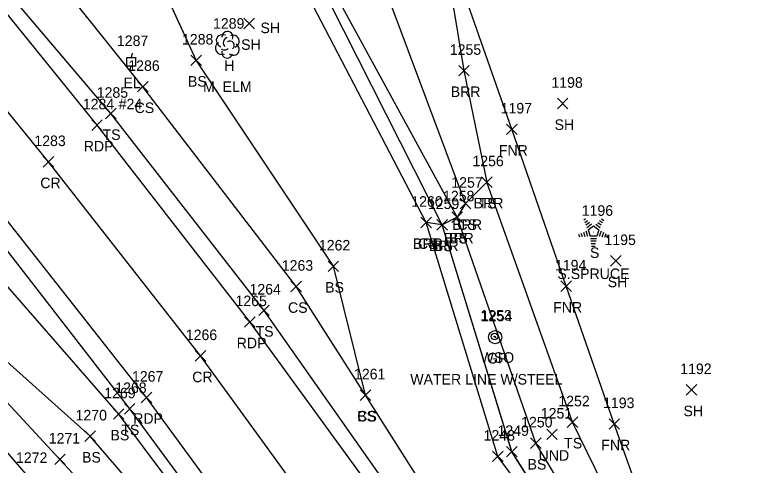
# Model space of a CAD drawing. Extents: x 1415642 to 1422021, y 544543 to 547232.
# Drawn here: x 1416364 to 1416506.8, y 546547.3 to 546632.9 of the extents above; entities that cross this region are included whole.
import ezdxf

# ---------------------------------------------------------------- set-up
doc = ezdxf.new("R2010")
doc.units = 0
for name, color, linetype in [('D_A', 7, 'Continuous'), ('D_I', 7, 'Continuous'), ('D_TIC', 7, 'Continuous'), ('L_A', 7, 'Continuous'), ('L_C', 7, 'Continuous'), ('L_I', 7, 'Continuous'), ('L_TIC', 7, 'Continuous'), ('LABL', 7, 'Continuous'), ('LAWA', 7, 'Continuous'), ('LELB', 7, 'Continuous'), ('LFNC', 7, 'Continuous'), ('LTC', 7, 'Continuous'), ('LTD', 7, 'Continuous'), ('P_A', 7, 'Continuous'), ('P_I', 7, 'Continuous'), ('P_TIC', 7, 'Continuous'), ('PET', 7, 'Continuous'), ('PRC', 7, 'Continuous'), ('R_A', 7, 'Continuous'), ('R_C', 7, 'Continuous'), ('R_I', 7, 'Continuous'), ('RGP', 7, 'Continuous'), ('U_A', 7, 'Continuous'), ('U_C', 7, 'Continuous'), ('U_I', 7, 'Continuous'), ('UEPT', 7, 'Continuous'), ('UWV', 7, 'Continuous')]:
    doc.layers.add(name, color=color, linetype=linetype)

msp = doc.modelspace()

# ---------------------------------------------------------------- linework, layer by layer
at = {"layer": 'D_TIC'}
for points in [[(1416464.81, 546552.27), (1416466.81, 546554.27)], [(1416466.81, 546552.27), (1416464.81, 546554.27)]]:
    msp.add_lwpolyline(points, dxfattribs=at)
at = {"layer": 'L_TIC'}
for points in [[(1416407.37, 546630.27), (1416409.37, 546632.27)], [(1416409.37, 546630.27), (1416407.37, 546632.27)], [(1416397.34, 546623.28), (1416399.34, 546625.28)], [(1416399.34, 546623.28), (1416397.34, 546625.28)], [(1416448.12, 546621.32), (1416450.12, 546623.32)], [(1416450.12, 546621.32), (1416448.12, 546623.32)], [(1416387.22, 546618.27), (1416389.22, 546620.27)], [(1416389.22, 546618.27), (1416387.22, 546620.27)], [(1416466.83, 546615.07), (1416468.83, 546617.07)], [(1416468.83, 546615.07), (1416466.83, 546617.07)], [(1416381.17, 546613.17), (1416383.17, 546615.17)], [(1416383.17, 546613.17), (1416381.17, 546615.17)], [(1416457.21, 546610.19), (1416459.21, 546612.19)], [(1416459.21, 546610.19), (1416457.21, 546612.19)], [(1416452.47, 546600.16), (1416454.47, 546602.16)], [(1416454.47, 546600.16), (1416452.47, 546602.16)], [(1416452.47, 546600.16), (1416454.47, 546602.16)], [(1416454.47, 546600.16), (1416452.47, 546602.16)], [(1416448.42, 546596.09), (1416450.42, 546598.09)], [(1416450.42, 546596.09), (1416448.42, 546598.09)], [(1416448.42, 546596.09), (1416450.42, 546598.09)], [(1416450.42, 546596.09), (1416448.42, 546598.09)], [(1416446.84, 546593.51), (1416448.84, 546595.51)], [(1416448.84, 546593.51), (1416446.84, 546595.51)], [(1416446.84, 546593.51), (1416448.84, 546595.51)], [(1416448.84, 546593.51), (1416446.84, 546595.51)], [(1416440.96, 546592.48), (1416442.96, 546594.48)], [(1416442.96, 546592.48), (1416440.96, 546594.48)], [(1416440.96, 546592.48), (1416442.96, 546594.48)], [(1416442.96, 546592.48), (1416440.96, 546594.48)], [(1416443.98, 546592.05), (1416445.98, 546594.05)], [(1416445.98, 546592.05), (1416443.98, 546594.05)], [(1416443.98, 546592.05), (1416445.98, 546594.05)], [(1416445.98, 546592.05), (1416443.98, 546594.05)], [(1416476.9, 546585.21), (1416478.9, 546587.21)], [(1416478.9, 546585.21), (1416476.9, 546587.21)], [(1416423.35, 546584.18), (1416425.35, 546586.18)], [(1416425.35, 546584.18), (1416423.35, 546586.18)], [(1416416.31, 546580.34), (1416418.31, 546582.34)], [(1416418.31, 546580.34), (1416416.31, 546582.34)], [(1416467.51, 546580.39), (1416469.51, 546582.39)], [(1416469.51, 546580.39), (1416467.51, 546582.39)], [(1416410.19, 546575.82), (1416412.19, 546577.82)], [(1416412.19, 546575.82), (1416410.19, 546577.82)], [(1416491.25, 546560.72), (1416493.25, 546562.72)], [(1416493.25, 546560.72), (1416491.25, 546562.72)], [(1416429.44, 546559.72), (1416431.44, 546561.72)], [(1416431.44, 546559.72), (1416429.44, 546561.72)], [(1416429.44, 546559.72), (1416431.44, 546561.72)], [(1416431.44, 546559.72), (1416429.44, 546561.72)], [(1416382.64, 546556.13), (1416384.64, 546558.13)], [(1416384.64, 546556.13), (1416382.64, 546558.13)], [(1416384.73, 546557.12), (1416386.73, 546559.12)], [(1416386.73, 546557.12), (1416384.73, 546559.12)], [(1416468.71, 546554.6), (1416470.71, 546556.6)], [(1416470.71, 546554.6), (1416468.71, 546556.6)], [(1416476.63, 546554.25), (1416478.63, 546556.25)], [(1416478.63, 546554.25), (1416476.63, 546556.25)], [(1416377.25, 546551.92), (1416379.25, 546553.92)], [(1416379.25, 546551.92), (1416377.25, 546553.92)], [(1416461.74, 546550.59), (1416463.74, 546552.59)], [(1416463.74, 546550.59), (1416461.74, 546552.59)], [(1416457.18, 546548.98), (1416459.18, 546550.98)], [(1416459.18, 546548.98), (1416457.18, 546550.98)], [(1416371.51, 546547.53), (1416373.51, 546549.53)], [(1416373.51, 546547.53), (1416371.51, 546549.53)], [(1416454.53, 546548.09), (1416456.53, 546550.09)], [(1416456.53, 546548.09), (1416454.53, 546550.09)]]:
    msp.add_lwpolyline(points, dxfattribs=at)
at = {"layer": 'LABL'}
for points in [[(1416444.47, 546650.39), (1416449.12, 546622.32), (1416453.47, 546601.16), (1416449.42, 546597.09), (1416447.84, 546594.51), (1416444.98, 546593.05), (1416441.96, 546593.48), (1416418.31, 546638.92), (1416405.03, 546665.65), (1416399.91, 546654.53), (1416396.19, 546650.28), (1416389.66, 546643.26), (1416382.8, 546639.59), (1416370.88, 546651.88), (1416331.53, 546697.52), (1416315.15, 546719.28), (1416313.42, 546715.93), (1416308.55, 546724.26), (1416301.62, 546736.74), (1416278.11, 546774.25)], [(1416444.47, 546650.39), (1416449.12, 546622.32), (1416453.47, 546601.16), (1416449.42, 546597.08), (1416447.84, 546594.51), (1416444.98, 546593.04), (1416441.96, 546593.48), (1416418.31, 546638.92), (1416405.03, 546665.65), (1416399.91, 546654.53), (1416396.19, 546650.28), (1416389.66, 546643.27), (1416382.81, 546639.59), (1416370.88, 546651.88), (1416331.54, 546697.52), (1416315.15, 546719.28), (1416313.42, 546715.93), (1416308.55, 546724.26), (1416301.62, 546736.74), (1416278.12, 546774.25)]]:
    msp.add_lwpolyline(points, dxfattribs=at)
at = {"layer": 'LAWA'}
msp.add_lwpolyline([(1416366.86, 546544.85), (1416337.81, 546578.41)], dxfattribs=at)
msp.add_lwpolyline([(1416366.86, 546544.85), (1416337.81, 546578.41)], dxfattribs=at)
at = {"layer": 'LELB'}
for points in [[(1416413.88, 546519.84), (1416385.73, 546558.12), (1416356.85, 546595.36), (1416336.82, 546621.39), (1416300.66, 546661.66), (1416278.22, 546684.25), (1416249.88, 546714.04), (1416230.93, 546728.9), (1416221.86, 546737.5), (1416200.69, 546756.25), (1416176.24, 546778.44), (1416157.26, 546793.38), (1416140.02, 546808.9), (1416121.84, 546825.58), (1416090.2, 546848.7), (1416061.67, 546872.28), (1416021.03, 546902.96), (1415979.27, 546932.57), (1415964.6, 546940.59)], [(1416413.88, 546519.84), (1416385.73, 546558.12), (1416356.85, 546595.36), (1416336.82, 546621.39), (1416300.66, 546661.66), (1416278.22, 546684.25), (1416249.88, 546714.04), (1416230.93, 546728.9), (1416221.87, 546737.51), (1416200.69, 546756.25), (1416176.24, 546778.44), (1416157.26, 546793.38), (1416140.03, 546808.9), (1416121.84, 546825.58), (1416090.21, 546848.7), (1416061.68, 546872.28), (1416021.04, 546902.96), (1415979.28, 546932.57), (1415964.61, 546940.59)], [(1416487.57, 546505.93), (1416480.71, 546505.12), (1416469.86, 546502.72), (1416462.76, 546510.55), (1416442.83, 546541.19), (1416430.44, 546560.72), (1416424.35, 546585.18), (1416398.34, 546624.28), (1416389.66, 546643.26), (1416377.3, 546653.03), (1416344.54, 546704.05), (1416343.42, 546724.77), (1416329.35, 546768.04), (1416303.68, 546799.52), (1416274.8, 546819.39), (1416239.26, 546839.41), (1416210.61, 546845.46), (1416203.47, 546849.21), (1416195, 546854.49)], [(1416487.57, 546505.93), (1416480.71, 546505.12), (1416469.86, 546502.72), (1416462.76, 546510.55), (1416442.83, 546541.19), (1416430.44, 546560.72), (1416424.35, 546585.18), (1416398.34, 546624.28), (1416389.66, 546643.27), (1416377.3, 546653.03), (1416344.54, 546704.05), (1416343.42, 546724.76), (1416329.35, 546768.04), (1416303.68, 546799.52), (1416274.8, 546819.4), (1416239.26, 546839.41), (1416210.61, 546845.46), (1416203.48, 546849.21), (1416195, 546854.49)], [(1416488.29, 546504.83), (1416488.12, 546506.46), (1416480.5, 546522.11), (1416462.74, 546551.59), (1416447.84, 546594.51), (1416422.44, 546641.16), (1416410.18, 546676.27), (1416393.07, 546713.79), (1416378.8, 546749.63), (1416367.97, 546783.97), (1416347.35, 546811.63), (1416340.26, 546839.45), (1416338.76, 546849.28)], [(1416488.29, 546504.83), (1416488.12, 546506.46), (1416480.5, 546522.11), (1416462.74, 546551.59), (1416447.84, 546594.51), (1416422.44, 546641.16), (1416410.17, 546676.27), (1416393.07, 546713.79), (1416378.8, 546749.63), (1416367.97, 546783.97), (1416347.34, 546811.63), (1416340.26, 546839.45), (1416338.76, 546849.28)], [(1416449.42, 546597.09), (1416431.29, 546645.7), (1416419.63, 546678.87), (1416400.37, 546718.89), (1416388.41, 546748.65), (1416375.25, 546786.59), (1416353.32, 546816.02), (1416347.15, 546837.59)], [(1416449.42, 546597.08), (1416431.29, 546645.7), (1416419.63, 546678.87), (1416400.37, 546718.89), (1416388.42, 546748.65), (1416375.25, 546786.59), (1416353.33, 546816.03), (1416347.15, 546837.59)], [(1416462.64, 546496.11), (1416437.87, 546538.89), (1416411.19, 546576.82), (1416382.17, 546614.17), (1416360.8, 546639.39), (1416323.65, 546683.15), (1416301.53, 546707.03), (1416273.6, 546735.69), (1416258.67, 546751.22), (1416224.41, 546784.74), (1416201.13, 546806.07), (1416169.09, 546832.26)], [(1416462.64, 546496.11), (1416437.87, 546538.89), (1416411.18, 546576.82), (1416382.17, 546614.17), (1416360.8, 546639.39), (1416323.65, 546683.15), (1416301.53, 546707.03), (1416273.6, 546735.69), (1416258.67, 546751.22), (1416224.4, 546784.74), (1416201.13, 546806.07), (1416169.09, 546832.26)], [(1416578, 546177.77), (1416578.55, 546199.27), (1416573.9, 546214.14), (1416552.43, 546269), (1416536.22, 546304.5), (1416520.22, 546335.71), (1416500.65, 546371.21), (1416484.25, 546405.14), (1416455.06, 546455.78), (1416435.93, 546486.65), (1416412.14, 546519.01), (1416383.64, 546557.13), (1416352.74, 546592.54), (1416331.82, 546618.14), (1416293.94, 546655.61), (1416274.22, 546680.91), (1416245.72, 546708.98), (1416224.27, 546729.93), (1416198.14, 546753.3), (1416170.94, 546765.48), (1416158.5, 546767.31), (1416141.08, 546772.75), (1416136.01, 546776.95), (1416129, 546780.64)], [(1416578, 546177.77), (1416578.55, 546199.27), (1416573.9, 546214.14), (1416552.42, 546269.01), (1416536.22, 546304.5), (1416520.22, 546335.71), (1416500.65, 546371.22), (1416484.25, 546405.15), (1416455.06, 546455.79), (1416435.93, 546486.65), (1416412.14, 546519.01), (1416383.65, 546557.13), (1416352.74, 546592.54), (1416331.82, 546618.14), (1416293.94, 546655.62), (1416274.22, 546680.91), (1416245.72, 546708.98), (1416224.27, 546729.93), (1416198.14, 546753.3), (1416170.94, 546765.48), (1416158.51, 546767.31), (1416141.09, 546772.75), (1416136.01, 546776.96), (1416129.01, 546780.64)], [(1416503.76, 546247.98), (1416498.74, 546274.69), (1416501.23, 546308.66), (1416502.98, 546324.04), (1416489.47, 546365.32), (1416480.57, 546403.46), (1416453.11, 546455.02), (1416433.2, 546484.78), (1416409.26, 546516.78), (1416378.25, 546552.92), (1416343.61, 546583.91), (1416327.57, 546614.09), (1416289.4, 546651.59), (1416267.58, 546675.69), (1416237.14, 546697.31), (1416220.66, 546725.9), (1416195.41, 546750.9), (1416170.78, 546763.33), (1416158.82, 546764.49), (1416140.16, 546770.72), (1416135.4, 546775.05), (1416128.27, 546778.63)], [(1416503.76, 546247.98), (1416498.74, 546274.69), (1416501.24, 546308.65), (1416502.98, 546324.03), (1416489.47, 546365.32), (1416480.57, 546403.46), (1416453.11, 546455.02), (1416433.2, 546484.78), (1416409.26, 546516.79), (1416378.25, 546552.92), (1416343.61, 546583.91), (1416327.58, 546614.09), (1416289.4, 546651.59), (1416267.58, 546675.69), (1416237.14, 546697.31), (1416220.66, 546725.9), (1416195.42, 546750.9), (1416170.78, 546763.33), (1416158.81, 546764.5), (1416140.16, 546770.72), (1416135.4, 546775.05), (1416128.28, 546778.62)], [(1416488.29, 546504.83), (1416487.21, 546504.52), (1416487.57, 546505.93), (1416477.24, 546519.91), (1416458.18, 546549.98), (1416444.98, 546593.05), (1416421.02, 546640.5), (1416406.73, 546674.57), (1416393.07, 546713.79)], [(1416488.29, 546504.83), (1416487.21, 546504.52), (1416487.57, 546505.93), (1416477.24, 546519.91), (1416458.18, 546549.99), (1416444.98, 546593.04), (1416421.01, 546640.5), (1416406.73, 546674.57), (1416393.07, 546713.79)], [(1416430.44, 546560.72), (1416417.31, 546581.34), (1416388.22, 546619.27), (1416367.45, 546645.31), (1416327.63, 546687.63), (1416307.15, 546711.36)], [(1416430.44, 546560.72), (1416417.31, 546581.35), (1416388.22, 546619.27), (1416367.44, 546645.31), (1416327.63, 546687.64), (1416307.15, 546711.36)], [(1416480.57, 546403.46), (1416449.3, 546452.17), (1416431.01, 546483.64), (1416405.55, 546512.84), (1416372.51, 546548.53), (1416341.49, 546581.99), (1416324.84, 546612.16), (1416286, 546648.13), (1416263.12, 546671.71)], [(1416480.57, 546403.46), (1416449.3, 546452.17), (1416431.01, 546483.64), (1416405.56, 546512.84), (1416372.51, 546548.53), (1416341.49, 546581.99), (1416324.84, 546612.16), (1416286, 546648.13), (1416263.12, 546671.71)], [(1416493.36, 546510.33), (1416486.81, 546520.52), (1416469.71, 546555.6), (1416453.47, 546601.16)], [(1416493.36, 546510.33), (1416486.82, 546520.52), (1416469.71, 546555.59), (1416453.47, 546601.16)], [(1416477.24, 546519.91), (1416455.53, 546549.09), (1416441.96, 546593.48)], [(1416477.24, 546519.91), (1416455.53, 546549.1), (1416441.96, 546593.48)]]:
    msp.add_lwpolyline(points, dxfattribs=at)
at = {"layer": 'LFNC'}
for points in [[(1416506.5, 546506.54), (1416496.1, 546503.23), (1416493.36, 546510.33), (1416488.7, 546524.12), (1416477.63, 546555.25), (1416468.51, 546581.39), (1416458.21, 546611.19), (1416444.47, 546650.39), (1416432.95, 546683.5)], [(1416506.5, 546506.54), (1416496.1, 546503.23), (1416493.36, 546510.33), (1416488.7, 546524.12), (1416477.63, 546555.24), (1416468.51, 546581.39), (1416458.21, 546611.19), (1416444.47, 546650.39), (1416432.95, 546683.5)]]:
    msp.add_lwpolyline(points, dxfattribs=at)
at = {"layer": 'LTC'}
for p, q in [((1416471.83, 546593.97), (1416472.18, 546594.22)), ((1416472.03, 546593.5), (1416472.56, 546593.89)), ((1416474.85, 546593.86), (1416475.4, 546593.46)), ((1416475.22, 546594.21), (1416475.64, 546593.9)), ((1416472.24, 546593.04), (1416472.95, 546593.55)), ((1416472.45, 546592.57), (1416473.33, 546593.21)), ((1416472.68, 546592.11), (1416473.69, 546592.85)), ((1416473.69, 546592.85), (1416474.69, 546592.12)), ((1416474.11, 546593.16), (1416474.92, 546592.57)), ((1416474.48, 546593.51), (1416475.16, 546593.02)), ((1416470.86, 546591.25), (1416471.01, 546590.78)), ((1416471.31, 546591.46), (1416471.52, 546590.81)), ((1416471.77, 546591.68), (1416472.04, 546590.84)), ((1416472.22, 546591.9), (1416472.55, 546590.88)), ((1416472.68, 546592.11), (1416473.07, 546590.92)), ((1416474.3, 546590.92), (1416473.07, 546590.92)), ((1416474.69, 546592.12), (1416474.3, 546590.92)), ((1416475.12, 546591.85), (1416474.79, 546590.81)), ((1416475.57, 546591.6), (1416475.28, 546590.72)), ((1416476.01, 546591.35), (1416475.78, 546590.62)), ((1416476.46, 546591.1), (1416476.27, 546590.53)), ((1416474.26, 546590.42), (1416473.11, 546590.42)), ((1416474.17, 546589.92), (1416473.19, 546589.92)), ((1416474.09, 546589.42), (1416473.26, 546589.42)), ((1416474.01, 546588.92), (1416473.33, 546588.92))]:
    msp.add_line(p, q, dxfattribs=at)
at = {"layer": 'LTD'}
msp.add_line((1416404.23, 546627.28), (1416404.23, 546627.28), dxfattribs=at)
msp.add_line((1416404.23, 546627.28), (1416404.23, 546627.28), dxfattribs=at)
msp.add_arc((1416404.27, 546628.71), 1.05, 335.5272, 180.9563, dxfattribs=at)
for centre, major_axis, ratio, start_param, end_param in [((1416403.44, 546627.95), (1.21, -0.51), 0.895232, 1.570796, 4.712389), ((1416404.02, 546627.74), (-0.208, -0.792), 0.645439, 3.141593, 6.283185), ((1416404.73, 546627.11), (-0.5, 0.667), 0.989748, 3.141593, 6.283185), ((1416405.27, 546627.86), (-1.14, -0.48), 0.949671, 1.570796, 4.712389), ((1416403.14, 546626.57), (0.58, -1.04), 0.959034, 3.141593, 6.283185), ((1416403.77, 546626.53), (-0.625, -0.083), 0.423636, 0, 3.141593), ((1416405.23, 546626.45), (-1.09, 0.79), 0.841452, 1.570796, 4.712389), ((1416404.23, 546625.78), (0.26, 1.06), 0.942809, 1.570796, 4.712389)]:
    msp.add_ellipse(centre, major_axis=major_axis, ratio=ratio, start_param=start_param, end_param=end_param, dxfattribs=at)
at = {"layer": 'P_TIC'}
for points in [[(1416378.54, 546610.97), (1416380.54, 546612.97)], [(1416380.54, 546610.97), (1416378.54, 546612.97)], [(1416369.34, 546604), (1416371.34, 546606)], [(1416371.34, 546604), (1416369.34, 546606)], [(1416407.53, 546573.61), (1416409.53, 546575.61)], [(1416409.53, 546573.61), (1416407.53, 546575.61)], [(1416398.16, 546567.17), (1416400.16, 546569.17)], [(1416400.16, 546567.17), (1416398.16, 546569.17)], [(1416387.9, 546559.28), (1416389.9, 546561.28)], [(1416389.9, 546559.28), (1416387.9, 546561.28)]]:
    msp.add_lwpolyline(points, dxfattribs=at)
at = {"layer": 'PET'}
for points in [[(1416435.56, 546537.44), (1416408.53, 546574.61), (1416379.54, 546611.97), (1416358.62, 546637.86), (1416320.38, 546681.18), (1416299.04, 546704.62), (1416270.68, 546734.26), (1416256.1, 546749.21), (1416221.42, 546781.44), (1416197.8, 546803.68), (1416167.45, 546829.93), (1416146.9, 546847.39), (1416116.66, 546870.72), (1416088.42, 546892.72), (1416062.97, 546911.59), (1416031.6, 546935.61), (1415998.08, 546959.73), (1415969.06, 546981.93), (1415936.64, 547006.92)], [(1416435.56, 546537.44), (1416408.53, 546574.62), (1416379.54, 546611.97), (1416358.63, 546637.85), (1416320.38, 546681.18), (1416299.04, 546704.62), (1416270.69, 546734.26), (1416256.1, 546749.21), (1416221.42, 546781.44), (1416197.8, 546803.68), (1416167.45, 546829.93), (1416146.9, 546847.38), (1416116.66, 546870.72), (1416088.42, 546892.72), (1416062.98, 546911.58), (1416031.6, 546935.61), (1415998.08, 546959.73), (1415969.07, 546981.93), (1415936.65, 547006.92)], [(1416417.68, 546520.98), (1416388.9, 546560.28), (1416359.4, 546597.75), (1416339.06, 546622.92), (1416303.08, 546664.45), (1416282.37, 546687.64), (1416253.58, 546717.16), (1416237.44, 546733.28), (1416206.51, 546762.17), (1416181.86, 546784.67), (1416151.94, 546810.47), (1416130.39, 546828.26), (1416101.49, 546851.34), (1416072.78, 546874.03), (1416047.41, 546892.82), (1416017.81, 546915.59), (1415982.21, 546942.39), (1415954.4, 546964.56)], [(1416417.68, 546520.98), (1416388.9, 546560.28), (1416359.4, 546597.76), (1416339.06, 546622.93), (1416303.08, 546664.45), (1416282.37, 546687.65), (1416253.58, 546717.16), (1416237.44, 546733.28), (1416206.51, 546762.17), (1416181.87, 546784.67), (1416151.94, 546810.47), (1416130.39, 546828.26), (1416101.49, 546851.34), (1416072.78, 546874.03), (1416047.41, 546892.82), (1416017.81, 546915.59), (1415982.21, 546942.39), (1415954.4, 546964.56)]]:
    msp.add_lwpolyline(points, dxfattribs=at)
at = {"layer": 'PRC'}
for points in [[(1416425.29, 546532.23), (1416399.16, 546568.17), (1416370.34, 546605), (1416349.98, 546630.03), (1416312.55, 546673.44), (1416291.21, 546696.63), (1416262.58, 546725.99), (1416246.66, 546742.06), (1416214.68, 546772.43), (1416190.4, 546794.67), (1416160.38, 546819.82), (1416139.01, 546837.64), (1416109.6, 546860.71), (1416080.51, 546883.13), (1416051.44, 546902.01), (1416024.84, 546926.07), (1415989.92, 546951.67), (1415962.46, 546973.18)], [(1416425.29, 546532.24), (1416399.16, 546568.17), (1416370.35, 546605), (1416349.98, 546630.03), (1416312.55, 546673.45), (1416291.21, 546696.63), (1416262.58, 546725.99), (1416246.66, 546742.06), (1416214.67, 546772.43), (1416190.4, 546794.67), (1416160.38, 546819.82), (1416139.01, 546837.64), (1416109.6, 546860.71), (1416080.51, 546883.13), (1416051.45, 546902.01), (1416024.84, 546926.07), (1415989.92, 546951.68), (1415962.46, 546973.18)]]:
    msp.add_lwpolyline(points, dxfattribs=at)
at = {"layer": 'RGP'}
msp.add_line((1416455.05, 546571.73), (1416455.05, 546571.73), dxfattribs=at)
for radius in [1.25, 0.0833]:
    msp.add_circle((1416455.05, 546571.73), radius, dxfattribs=at)
at = {"layer": 'UEPT'}
for p, q in [((1416386.17, 546625.66), (1416386, 546624.83)), ((1416385.17, 546623.16), (1416385.17, 546624.83)), ((1416385.17, 546624.83), (1416386.84, 546624.83)), ((1416386, 546623.99), (1416386, 546623.99)), ((1416386.84, 546624.83), (1416386.84, 546623.16)), ((1416386.84, 546623.16), (1416385.17, 546623.16)), ((1416385.75, 546622.33), (1416386, 546623.16))]:
    msp.add_line(p, q, dxfattribs=at)
at = {"layer": 'UWV'}
for radius in [0.625, 0.0833]:
    msp.add_circle((1416454.92, 546571.86), radius, dxfattribs=at)

# ---------------------------------------------------------------- texts
at = {"layer": 'D_A'}
msp.add_text('UND', height=2, dxfattribs=at).set_placement((1416463.28, 546548.27))
at = {"layer": 'D_I'}
msp.add_text('1251', height=2, dxfattribs=at).set_placement((1416463.69, 546556.27))
at = {"layer": 'L_A'}
for s, p in [('SH', (1416410.53, 546629.44)), ('SH', (1416406.86, 546626.27)), ('H', (1416403.66, 546622.28)), ('BS', (1416396.78, 546619.28)), ('BRR', (1416446.61, 546617.32)), ('CS', (1416386.66, 546614.27)), ('SH', (1416466.31, 546611.07)), ('TS', (1416380.58, 546609.17)), ('FNR', (1416455.74, 546606.19)), ('BRR', (1416450.96, 546596.16)), ('TS', (1416451.88, 546596.16)), ('BRR', (1416446.9, 546592.09)), ('CS', (1416447.86, 546592.09)), ('BRR', (1416445.33, 546589.51)), ('BS', (1416446.28, 546589.51)), ('BRR', (1416439.45, 546588.48)), ('CS', (1416440.4, 546588.48)), ('BRR', (1416442.47, 546588.05)), ('BS', (1416443.42, 546588.05)), ('S', (1416473.02, 546586.76)), ('SH', (1416476.38, 546581.21)), ('BS', (1416422.79, 546580.18)), ('CS', (1416415.75, 546576.34)), ('FNR', (1416466.04, 546576.39)), ('TS', (1416409.6, 546571.82)), ('SH', (1416490.74, 546556.72)), ('CS', (1416428.88, 546555.72)), ('BS', (1416428.88, 546555.72)), ('BS', (1416382.09, 546552.13)), ('TS', (1416384.13, 546553.12)), ('TS', (1416468.12, 546550.6)), ('FNR', (1416475.16, 546550.25)), ('BS', (1416376.69, 546547.92)), ('BS', (1416461.18, 546546.59))]:
    msp.add_text(s, height=2, dxfattribs=at).set_placement(p)
at = {"layer": 'L_C'}
for s, p in [('M. ELM', (1416399.64, 546618.28)), ('S.SPRUCE', (1416466.84, 546582.76))]:
    msp.add_text(s, height=2, dxfattribs=at).set_placement(p)
at = {"layer": 'L_I'}
for s, p in [('1289', (1416401.53, 546630.28)), ('1288', (1416395.65, 546627.28)), ('1255', (1416446.43, 546625.32)), ('1286', (1416385.47, 546622.27)), ('1198', (1416465.7, 546619.07)), ('1285', (1416379.48, 546617.17)), ('1197', (1416456.08, 546614.19)), ('1256', (1416450.72, 546604.16)), ('1256', (1416450.72, 546604.16)), ('1257', (1416446.72, 546600.09)), ('1257', (1416446.72, 546600.09)), ('1258', (1416445.15, 546597.51)), ('1258', (1416445.15, 546597.51)), ('1260', (1416439.14, 546596.48)), ('1260', (1416439.14, 546596.48)), ('1259', (1416442.28, 546596.05)), ('1259', (1416442.28, 546596.05)), ('1196', (1416471.45, 546594.76)), ('1195', (1416475.77, 546589.21)), ('1262', (1416421.61, 546588.18)), ('1263', (1416414.57, 546584.34)), ('1194', (1416466.38, 546584.39)), ('1264', (1416408.45, 546579.82)), ('1192', (1416490.13, 546564.72)), ('1261', (1416428.27, 546563.72)), ('1261', (1416428.27, 546563.72)), ('1268', (1416382.99, 546561.12)), ('1269', (1416380.9, 546560.13)), ('1252', (1416467.02, 546558.6)), ('1193', (1416475.5, 546558.25)), ('1270', (1416375.47, 546555.92)), ('1250', (1416459.96, 546554.59)), ('1248', (1416452.84, 546552.09)), ('1249', (1416455.48, 546552.98)), ('1271', (1416370.38, 546551.53)), ('1272', (1416364.17, 546547.85))]:
    msp.add_text(s, height=2, dxfattribs=at).set_placement(p)
at = {"layer": 'LTC'}
msp.add_text('.', height=1.04, rotation=270, dxfattribs=at).set_placement((1416473.57, 546591.86))
at = {"layer": 'P_A'}
for s, p in [('RDP', (1416377.02, 546606.97)), ('CR', (1416368.78, 546600)), ('RDP', (1416406.02, 546569.61)), ('CR', (1416397.59, 546563.17)), ('RDP', (1416386.39, 546555.28))]:
    msp.add_text(s, height=2, dxfattribs=at).set_placement(p)
at = {"layer": 'P_I'}
for s, p in [('1284', (1416376.84, 546614.97)), ('1283', (1416367.65, 546608)), ('1265', (1416405.79, 546577.61)), ('1266', (1416396.37, 546571.17)), ('1267', (1416386.16, 546563.28))]:
    msp.add_text(s, height=2, dxfattribs=at).set_placement(p)
at = {"layer": 'R_A'}
msp.add_text('GP', height=2, dxfattribs=at).set_placement((1416453.49, 546566.73))
at = {"layer": 'R_C'}
msp.add_text('WATER LINE W/STEEL', height=2, dxfattribs=at).set_placement((1416438.94, 546562.73))
at = {"layer": 'R_I'}
msp.add_text('1254', height=2, dxfattribs=at).set_placement((1416452.36, 546574.73))
at = {"layer": 'U_A'}
for s, p in [('EL', (1416384.54, 546618.99)), ('WSO', (1416452.25, 546566.86))]:
    msp.add_text(s, height=2, dxfattribs=at).set_placement(p)
at = {"layer": 'U_C'}
msp.add_text('#24', height=2, dxfattribs=at).set_placement((1416383.64, 546614.99))
at = {"layer": 'U_I'}
for s, p in [('1287', (1416383.31, 546626.99)), ('1253', (1416452.23, 546574.86))]:
    msp.add_text(s, height=2, dxfattribs=at).set_placement(p)

doc.saveas('drawing.dxf')
